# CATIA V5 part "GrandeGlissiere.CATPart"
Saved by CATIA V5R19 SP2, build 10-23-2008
Part number: GrandeGlissiere
Bounding box of the stored display mesh (mm): x 0 to 10, y -70 to 70, z -40 to 40
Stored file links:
  D:\SCHOOL\FRANCE\BANC_POUTRE_EN_MOUSSE\GrandeGlissiere.CATPart
  C:\Program Files\Dassault Systemes\B19\intel_a\reffiles\standard\MetricThickPitch.txt
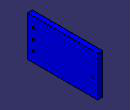
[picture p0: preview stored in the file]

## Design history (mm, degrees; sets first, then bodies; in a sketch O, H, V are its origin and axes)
AxisSystem1: origin (0, 0, 0), X (1, 0, 0), Y (0, 1, 0), Z (0, 0, 1)
Body1 (main body)
  Sketch1 on YZ plane of AxisSystem1, origin (0, 0, 0), H (0, 1, 0), V (0, 0, 1)
    line L1 (70, 40) -> (70, -40)
    line L2 (70, -40) -> (-70, -40)
    line L3 (-70, -40) -> (-70, 40)
    line L4 (-70, 40) -> (70, 40)
    length L4 = 140
    length L1 = 80
    vertical: L1 V, L3 V
    horizontal: L2 H, L4 H
    equidistance: L1 L3 O, L2 L4 O
  Pad1: profile Sketch1, direction (1, 0, 0), length 10
  Sketch2 on start face of Pad1, origin (0, -57.8553, -24.1337), H (0, 1, 0), V (0, 0, -1)
    point P1 (-0.1447, -4.1337)
    reference projected line E1 (-12.1447, -64.1337) -> (-12.1447, 15.8663) from edge [start face of Pad1 | face of Pad1 from Sketch1.L3]
    reference projected line E2 (-12.1447, 15.8663) -> (127.8553, 15.8663) from edge [start face of Pad1 | face of Pad1 from Sketch1.L2]
    distance E1 P1 = 12
    distance E2 P1 = 20
  Hole1: placed by Sketch2, at (0, -58, -20) direction (1, 0, 0), diameter 4.917, through (limit type 3), counterbore diameter 10, counterbore depth 5
  RectPattern1: of Hole1, direction 1 instances 2, spacing 40, along edge [start face of Pad1 | face of Pad1 from Sketch1.L3] reversed
  Sketch3 on start face of Pad1, origin (0, -57.9977, -0.2981), H (0, 1, 0), V (0, 0, -1)
    point P1 (-0.0023, -0.2981)
    axis line L1 (-70.0023, -0.2981) -> (159.9977, -0.2981)
    reference projected line E1 (-12.0023, -40.2981) -> (-12.0023, 39.7019) from edge [start face of Pad1 | face of Pad1 from Sketch1.L3]
    reference intersected line E2 through (0, -0.2981) direction (1, 0) from XY plane of AxisSystem1
    distance E1 P1 = 12
    horizontal: L1 H
    coincidence: L1 P1, E2 L1
  Hole2: placed by Sketch3, at (0, -58, 0) direction (1, 0, 0), diameter 4.917, through (limit type 3), counterbore diameter 10, counterbore depth 5
  Sketch4 on end face of Pad1, origin (10, 60.7809, 31.9333), H (0, 1, 0), V (0, 0, 1)
    point P1 (-0.7809, -36.9333)
    reference projected line E1 (9.2191, 8.0667) -> (-130.7809, 8.0667) from edge [face of Pad1 from Sketch1.L4 | end face of Pad1]
    reference projected line E2 (9.2191, -71.9333) -> (9.2191, 8.0667) from edge [face of Pad1 from Sketch1.L1 | end face of Pad1]
    distance E1 P1 = 45
    distance P1 E2 = 10
  Hole3: placed by Sketch4, at (10, 60, -5) direction (-1, 0, 0), diameter 4.917, through (limit type 3)
  Sketch5 on start face of Pad1, origin (0, 16.6017, -9.9952), H (0, 1, 0), V (0, 0, -1)
    point P1 (-6.6017, 15.0048)
    reference projected line E1 (-86.6017, 30.0048) -> (53.3983, 30.0048) from edge [start face of Pad1 | face of Pad1 from Sketch1.L2]
    reference projected line E2 (53.3983, 30.0048) -> (53.3983, -49.9952) from edge [start face of Pad1 | face of Pad1 from Sketch1.L1]
    distance P1 E1 = 15
    distance E2 P1 = 60
  Hole4: placed by Sketch5, at (0, 10, -25) direction (1, 0, 0), diameter 10.106, depth 8, threaded "M12", thread diameter 12, thread depth 8, pitch 1.75
  RectPattern2: of Hole4, direction 1 instances 2, spacing 40, along edge [start face of Pad1 | face of Pad1 from Sketch1.L2] reversed, direction 2 instances 2, spacing 50, along edge [start face of Pad1 | face of Pad1 from Sketch1.L1]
